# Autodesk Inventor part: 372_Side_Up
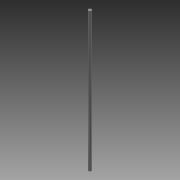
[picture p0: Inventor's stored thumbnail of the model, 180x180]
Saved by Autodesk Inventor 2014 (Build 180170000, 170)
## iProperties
Created: 2013-12
Part Number: 372_Side_Up
Material: Stainless Steel
Document SubType Name: Modeling
Designer: Bram
Density: 8.08 g/cm^3
Appearance: Semi-Polished
Author: Bram
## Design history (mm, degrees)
sketch "Sketch1"
  geometry: C1 r 4 at (0, 0); 1 further point
  constraints: 1 centre point, 1 coincident
  dimensions: "d0" = 8 diameter of C1
extrude "Extrusion1" new body sketch "Sketch1" distance "d1" = 372; taper "d2" = 0 deg
body "Solid1"
